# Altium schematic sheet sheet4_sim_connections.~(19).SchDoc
size A3; Author: Mauri Shadi; CompanyName: BFH; DrawnBy: Mauri Shadi; SheetNumber: 1; SheetTotal: 2
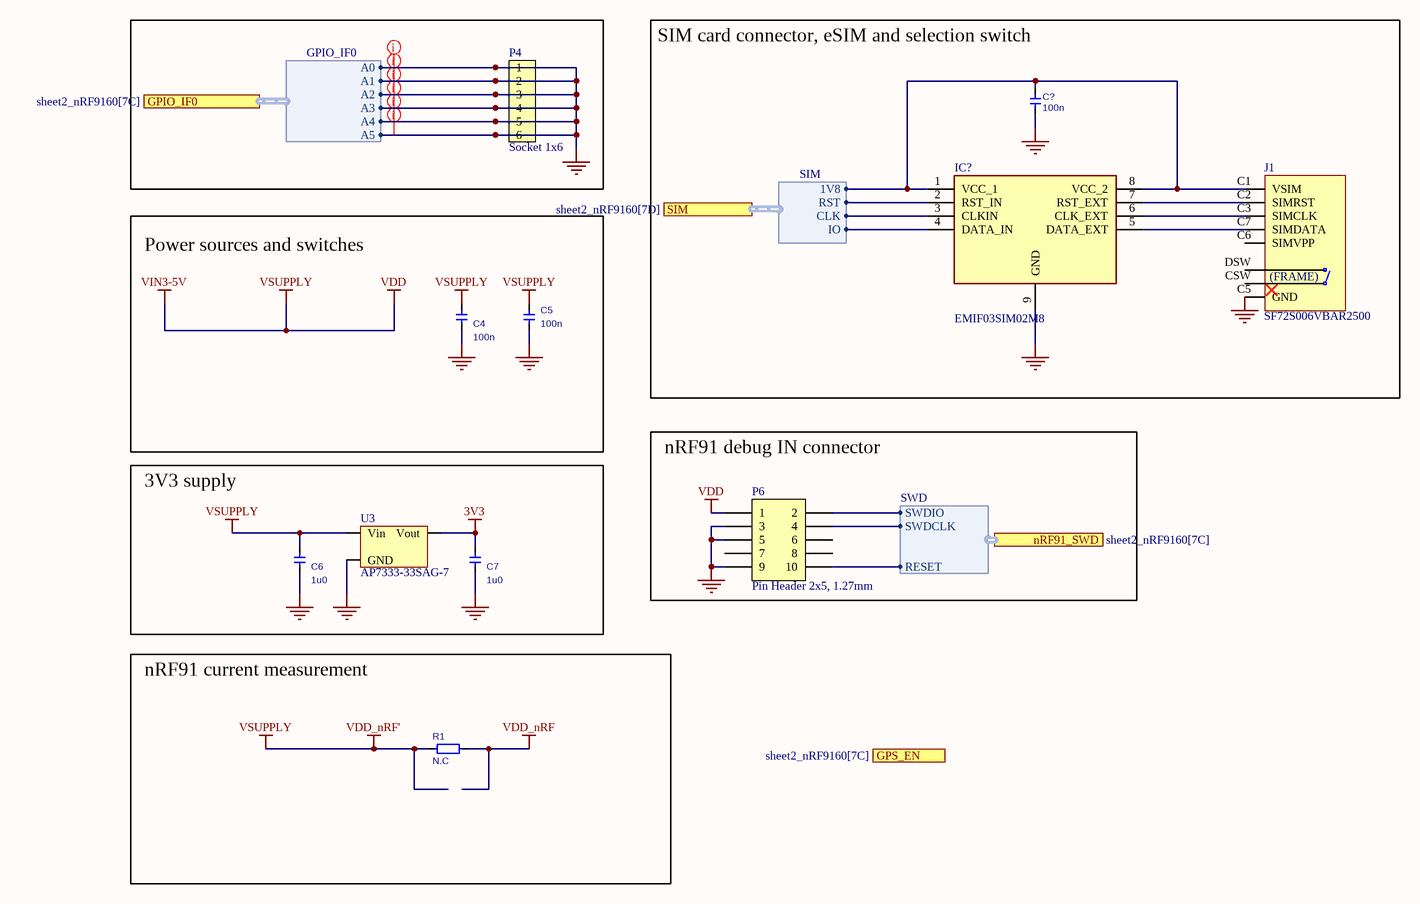
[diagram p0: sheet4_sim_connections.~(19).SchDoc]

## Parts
C4  100n  [0603(1608)C]
C5  100n  [0603(1608)C]
C6  1u0  [0603(1608)C]
C7  1u0  [0603(1608)C]
C?  100n  [0603(1608)C]
IC?  EMIF03SIM02M8  [SON40P150X170X60-9N-D]
J1  SF72S006VBAR2500  [SF72S006VBAR2500]
P4  Socket 1x6  [SOCKET_1x6_SMD]
P6  Pin Header 2x5, 1.27mm  [HDR_2x5-SMD-1.27mm-K]
R1  N.C  [0603(1608)]
U3  AP7333-33SAG-7  [SOT-23A]

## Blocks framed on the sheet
SIM card connector, eSIM and selection switch: C? IC? J1
Power sources and switches: C4 C5
nRF91 debug IN connector: P6
3V3 supply: C6 C7 U3
nRF91 current measurement: R1

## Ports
GPIO_IF0 (harness GPIO_IF0, see sheet2_nRF9160[7C]), GPS_EN (out, see sheet2_nRF9160[7C]), nRF91_SWD (harness SWD, see sheet2_nRF9160[7C]), SIM (harness SIM, see sheet2_nRF9160[7D])

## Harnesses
SWD: SWDIO, SWDCLK, RESET
GPIO_IF0: A0, A1, A2, A3, A4, A5
SIM: CLK, IO, 1V8, RST

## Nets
3V3: C7.1 U3.2(Vout)
GND: C4.2 C5.1 C6.2 C7.2 C?.1 IC?.9(GND) J1.0(GND) J1.C5(GND) P4.1 P4.2 P4.3 P4.4 P4.5 P4.6 P6.3 P6.5 P6.9 U3.3(GND) ; port GPIO_IF0.A0, port GPIO_IF0.A1, port GPIO_IF0.A2, port GPIO_IF0.A3, port GPIO_IF0.A4, port GPIO_IF0.A5
VDD: C4.1 C5.2 C6.1 P6.1 R1.2 U3.1(Vin)  [also labelled VDD_nRF', VIN3-5V, VSUPPLY]
VDD_nRF: R1.1
NetC?_2: C?.2 IC?.1(VCC_1) IC?.8(VCC_2) J1.C1(VSIM) ; port SIM.1V8
NetIC?_2: IC?.2(RST_IN) ; port SIM.RST
NetIC?_3: IC?.3(CLKIN) ; port SIM.CLK
NetIC?_4: IC?.4(DATA_IN) ; port SIM.IO
NetIC?_5: IC?.5(DATA_EXT) J1.C7(SIMDATA)
NetIC?_6: IC?.6(CLK_EXT) J1.C3(SIMCLK)
NetIC?_7: IC?.7(RST_EXT) J1.C2(SIMRST)
NetP6_2: P6.2 ; port nRF91_SWD.SWDIO
NetP6_4: P6.4 ; port nRF91_SWD.SWDCLK
NetP6_10: P6.10 ; port nRF91_SWD.RESET

Not connected (* = marked no-connect by the designer): J1 C6(SIMVPP) CSW DSW; P6 6 7 8

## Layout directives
net class GPIO: GND

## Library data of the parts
C4 C5 = C0603_5_100n_25V: Cer Chip Capacitor / 100n/ +-5%/ 25V; Manufacturer Part Number: CC0603KRX7R8BB104; Manufacturer 1: Yageo; Special Value 1: +-5%; Capacitance: 100nF; Tolerance: 10%; Dielectric: X7R
C6 C7 = C0603_6_1u0_25V: Cer Chip Capacitor / 1u0 / +-10%/ 25V; Manufacturer Part Number: CL10B105KA8VPNC; Manufacturer 1: Samsung; Special Value 1: +-10%; Capacitance: 1uF; Tolerance: 10%
C? = C0603_5_100n_25V: Cer Chip Capacitor / 100n/ +-5%/ 25V; Manufacturer 1: Yageo; Manufacturer Part Number: CC0603KRX7R8BB104; Special Value 1: +-5%; Capacitance: 100nF; Tolerance: 10%; Dielectric: X7R
IC? = EMIF03SIM02M8: Integrated Circuit; Manufacturer_Name: STMicroelectronics
J1 = SF72S006VBAR2500: n 8 (6 + 2) Position Card Connector NANO SIM Surface Mount, Right Angle Gold; Manufacturer: JAE Electronics; Part number IPS: 00000009956; Note: N.A.; Pad Count: 8
P4 = Socket 1x6 SMD: Socket 1x6, 2.54mm (100mil), SMD; Manufacturer: W-CON; Manufacturer Part Number: 2171-106MS0CUNR1; Part number IPS: 00000009964; Note: N.A.; Artikkelnr Noca: 55030001; Pad Count: 6
P6 = Pin Header 2x5 SMD, 1.27mm, KS: Pin Header 2x5, 1.27mm (50mil), SMD, Keying Shroud; Manufacturer: W-CON; Manufacturer Part Number: 3132-10MS0BK00R1; Part number IPS: 00000009968; Note: N.A.; Artikkelnr Noca: 55010009; Pad Count: 10
R1 = R0603_0_0E: Chip Resistor / 0E / 1% / 50V / 100mW / 0603(1608); Manufacturer Part Number: ERJ-3GEY0R00V; Manufacturer 1: Panasonic; Resistance: 0mR; Voltage Rating: 75V; Tolerance: 0%; Temperature Coefficient: 600ppm/°C
U3 = AP7333-33SAG-7: 300mA, Low Quiescent Current, Fast Transient Low Dropout Linear Regulator; Manufacturer: Diodes Incorporated; Part number IPS: 00000001673; Note: N.A.; Artikkelnr Noca: 17039216; Pad Count: 3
